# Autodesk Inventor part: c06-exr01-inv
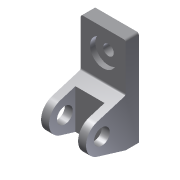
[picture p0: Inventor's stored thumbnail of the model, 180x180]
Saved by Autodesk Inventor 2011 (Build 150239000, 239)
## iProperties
Shininess: 77.0
Length Units: 11269
Angle Units: 11279
Time Units: 11290
Mass Units: 11283
Length Display Precision: 3
Angle Display Precision: 2
Created: 2001-12
Part Number: c06-exr01-inv
Document SubType Name: Modeling
Designer: Renu Muthoo
Density: 1 g/cm^3
Density: 0.0
Volumn: 0.0
Area: 0.0
PropertySet Name: Model Information
Control State: 0
Master: False
Checked Out: False
Author: Renu Muthoo
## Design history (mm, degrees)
node "Sketch1"
sketch "Sketch2"
  geometry: L1 (-8.12, 12.649)-(-8.12, 102.649); L2 (-8.12, 102.649)-(16.88, 102.649); L3 (16.88, 102.649)-(16.88, -77.351); L4 (16.88, -77.351)-(-8.12, -77.351); L5 (-8.12, -77.351)-(-61.829, -61.06); L6 (-61.829, -3.643)-(-8.12, 12.649); C1 r 15 at (-53.12, -32.351); A1 r 30 centre (-53.12, -32.351) between (-61.829, -3.643) and (-61.829, -61.06)
  constraints: 12 end point, 2 centre point, 2 equal length, 2 parallel, 2 point on circle, 2 tangent, 1 coincident, 1 perpendicular, 1 vertical
  dimensions: "d0" = 180 distance of L2.end L3.end; "d1" = 25 distance of L3.end L4.end; "d2" = 70 distance from line of L3 A1.centre; "d3" = 30 radius of A1; "d4" = 45 distance from line of L4 A1.centre; "d5" = 30 diameter of C1
extrude "Extrusion1" new body sketch "Sketch2" stored distance "d6" = 85; taper "d7" = 0 deg
sketch "Sketch3"
  geometry: L1 (-95, 20)-(-33.12, 20); L2 (-33.12, 20)-(-33.12, -81); L3 (-33.12, -81)-(-95, -81); L4 (-95, -81)-(-95, 20); C1 r 15 at (-53.12, -32.351) reference
  constraints: 8 end point, 2 parallel, 1 horizontal, 1 perpendicular
  dimensions: "d8" = 20 distance from line of C1.centre L2
extrude "Extrusion2" cut sketch "Sketch3" stored distance "d9" = 55; taper "d10" = 0 deg
sketch "Sketch4"
  geometry: L1 (85, -90)-(85, 0) reference; L2 (85, 0)-(0, 0) reference; 1 further point
  dimensions: "d11" = 42 distance from line of L2 point (42.5, -42); "d12" = 42.5 distance from line of L1 point (42.5, -42)
hole "Hole1" sketch "Sketch4" at (42.5, -42) diameter "d13" = 20; stored, may be unused: countersink angle "d17" = 82 deg, drill point angle "d19" = 118 deg; dims "d14" = 6, "d15" = 50, "d16" = 10, "d18" = 8
fillet "Fillet1" dims "d20" = 4, "d21" = 4
body "Solid1"
